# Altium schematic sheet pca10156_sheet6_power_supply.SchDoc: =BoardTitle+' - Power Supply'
size A3; Organization: Nordic Semiconductor; DocumentNumber: 6; SheetNumber: 6; SheetTotal: 7; CompanyName: Nordic Semiconductor; DocumentSize: A4
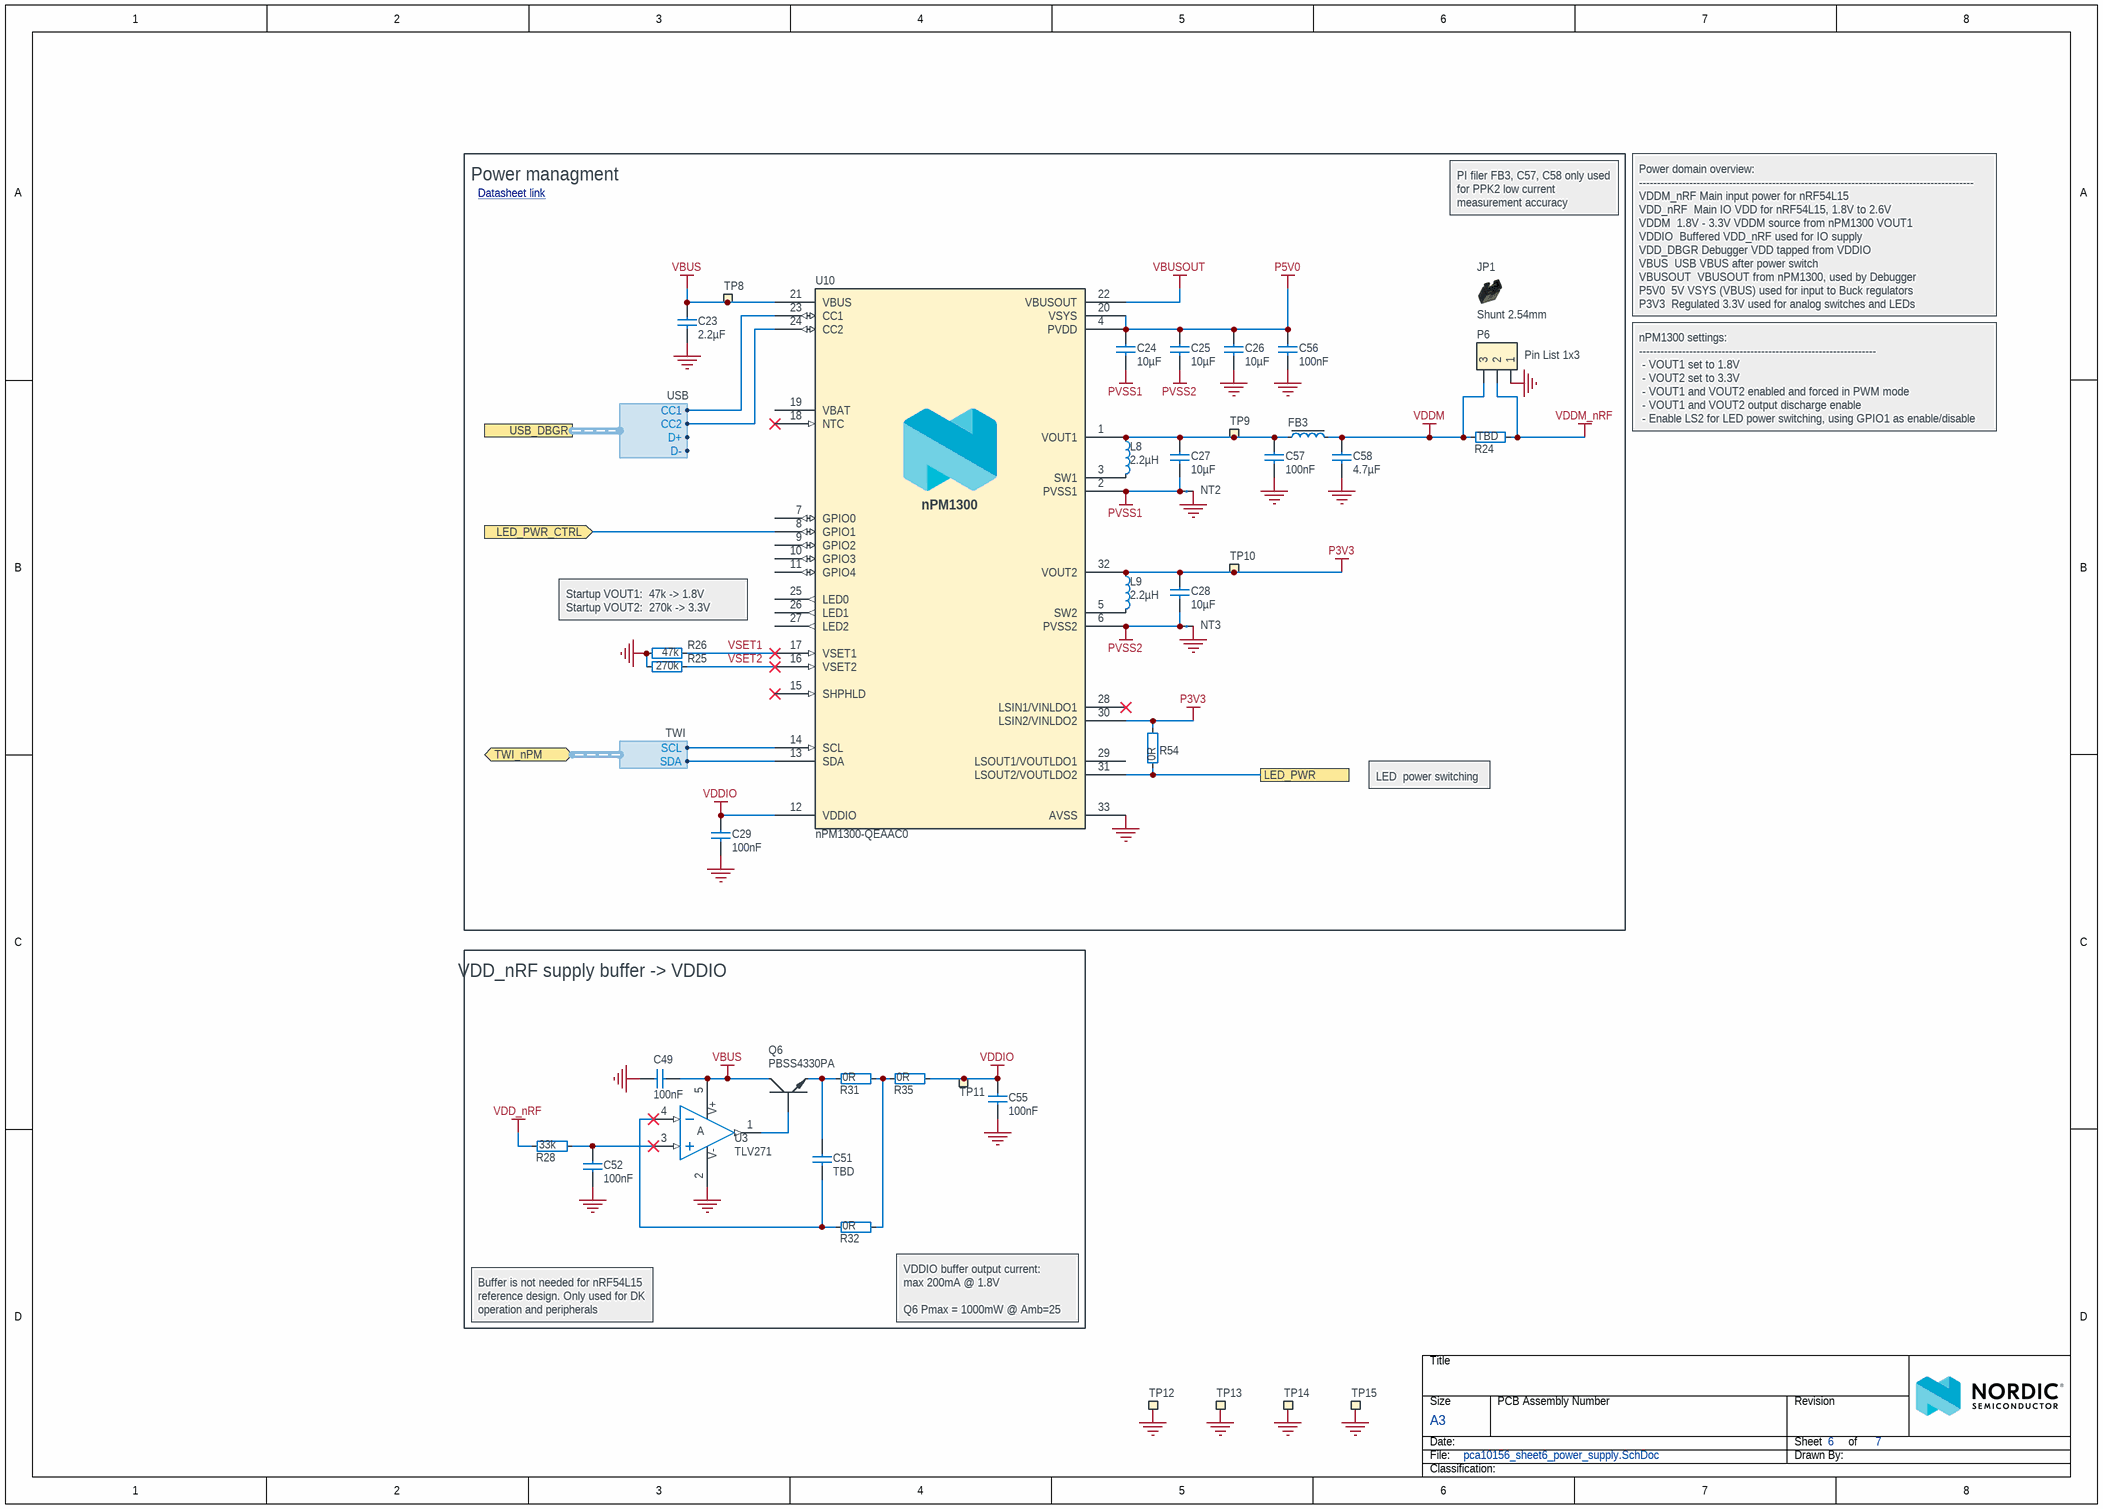
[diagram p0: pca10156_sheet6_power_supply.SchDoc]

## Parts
C23  2.2µF  [CAPC1005X04L]
C24  10µF  [CAPC1608X06L]
C25  10µF  [CAPC1608X06L]
C26  10µF  [CAPC1608X06L]
C27  10µF  [CAPC1608X06L]
C28  10µF  [CAPC1608X06L]
C29  100nF  [CAPC0603X03L_C]
C49  100nF  [CAPC0603X03L_C]
C51  TBD  [CAPC0603X03L_C]
C52  100nF  [CAPC0603X03L_C]
C55  100nF  [CAPC0603X03L_C]
C56  100nF  [CAPC0603X03L_C]
C57  100nF  [CAPC0603X03L_C]
C58  4.7µF  [CAPC1608X06L]
FB3  120R/0.55A  [INDC1005X04L]  (value not drawn)
JP1  Shunt 2.54mm  [Shunt_2.54mm_Vertical]
L8  2.2µH  [INDC2016X10N]
L9  2.2µH  [INDC2016X10N]
NT2  Net tie  [2 PIN STARPOINT]  (value not drawn)  (net tie, no BOM)
NT3  Net tie  [2 PIN STARPOINT]  (value not drawn)  (net tie, no BOM)
P6  Pin List 1x3  [LIST_1x3_SMD]
Q6  PBSS4330PA  [DFN105P200X65-3N_v2]
R24  TBD  [RESC1005X04L]
R25  270k  [RESC0603X03L_C]
R26  47k  [RESC0603X03L_C]
R28  33k  [RESC0603X03L_C]
R31  0R  [RESC0603X03L_C]
R32  0R  [RESC0603X03L_C]
R35  0R  [RESC0603X03L_C]
R54  0R  [RESC0603X03L_C]
TP8  Ø1.5mm,SMD  [TP_SMD_D1.5mm]  (value not drawn)  (no BOM)
TP9  Ø1.5mm,SMD  [TP_SMD_D1.5mm]  (value not drawn)  (no BOM)
TP10  Ø1.5mm,SMD  [TP_SMD_D1.5mm]  (value not drawn)  (no BOM)
TP11  Ø1.5mm,SMD  [TP_SMD_D1.5mm]  (value not drawn)  (no BOM)
TP12  Ø1.5mm,SMD  [TP_SMD_D1.5mm]  (value not drawn)  (no BOM)
TP13  Ø1.5mm,SMD  [TP_SMD_D1.5mm]  (value not drawn)  (no BOM)
TP14  Ø1.5mm,SMD  [TP_SMD_D1.5mm]  (value not drawn)  (no BOM)
TP15  Ø1.5mm,SMD  [TP_SMD_D1.5mm]  (value not drawn)  (no BOM)
U3  TLV271  [SOT95P280X145-5N]
U10  nPM1300-QEAAC0  [Nordic_QFN50P500X500X90-33N]

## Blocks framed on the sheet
Power managment: C23-C29 C56-C58 FB3 JP1 L8 L9 NT2 NT3 P6 R24-R26 R54 TP8-TP10 U10
VDD_nRF supply buffer -> VDDIO: C49 C51 C52 C55 Q6 R28 R31 R32 R35 TP11 U3

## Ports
LED_PWR, LED_PWR_CTRL (in), TWI_nPM (bidir, harness TWI), USB_DBGR (harness USB)

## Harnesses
TWI: SDA, SCL
USB: D+, D-, CC1, CC2

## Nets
GND: C23.1 C26.1 C29.2 C49.2 C52.2 C55.2 C56.1 C57.1 C58.2 NT2.1 NT3.1 P6.1 R25.2 R26.2 TP12.1 TP13.1 TP14.1 TP15.1 U3.2(VSS) U10.33(AVSS)
P3V3: C28.2 L9.1 R54.2 TP10.1 U10.30(LSIN2/VINLDO2) U10.32(VOUT2)
P5V0: C24.2 C25.2 C26.2 C56.2 U10.4(PVDD) U10.20(VSYS)
PVSS1: C24.1 C27.1 NT2.2 U10.2(PVSS1)
PVSS2: C25.1 C28.1 NT3.2 U10.6(PVSS2)
VBUS: C23.2 C49.1 Q6.3(C) TP8.1 U3.5(VDD) U10.21(VBUS)
VBUSOUT: U10.22(VBUSOUT)
VDD_nRF: R28.1
VDDIO: C29.1 C55.1 R35.2 TP11.1 U10.12(VDDIO)
VDDM: C58.1 FB3.2 P6.3 R24.2
VDDM_nRF: P6.2 R24.1
LED_PWR: R54.1 U10.31(LSOUT2/VOUTLDO2) ; port LED_PWR
LED_PWR_CTRL: U10.8(GPIO1) ; port LED_PWR_CTRL
VSET1: R26.1 U10.17(VSET1)
VSET2: R25.1 U10.16(VSET2)
NetC27_2: C27.2 C57.2 FB3.1 L8.1 TP9.1 U10.1(VOUT1)
NetC51_1: C51.1 R32.1 U3.4(IN-)
NetC51_2: C51.2 Q6.2(E) R31.1
NetC52_1: C52.1 R28.2 U3.3(IN+)
NetL8_2: L8.2 U10.3(SW1)
NetL9_2: L9.2 U10.5(SW2)
NetQ6_1: Q6.1(B) U3.1(OUT)
NetR31_2: R31.2 R32.2 R35.1
NetU10_13: U10.13(SDA) ; port TWI_nPM.SDA
NetU10_14: U10.14(SCL) ; port TWI_nPM.SCL
NetU10_23: U10.23(CC1) ; port USB_DBGR.CC1
NetU10_24: U10.24(CC2) ; port USB_DBGR.CC2

Not connected (* = marked no-connect by the designer): U10 7(GPIO0) 9(GPIO2) 10(GPIO3) 11(GPIO4) 15(SHPHLD)* 18(NTC)* 19(VBAT) 25(LED0) 26(LED1) 27(LED2) 28(LSIN1/VINLDO1)* 29(LSOUT1/VOUTLDO1)

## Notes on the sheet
- Datasheet link <https://infocenter.nordicsemi.com/index.jsp?topic=%2Fstruct_pmic%2Fstruct%2Fnpm1300.html>
- PI filer FB3, C57, C58 only used for PPK2 low current measurement accuracy
- Power domain overview:
  ---------------------------------------------------------------------------------------------
  VDDM_nRF	Main input power for nRF54L15
  VDD_nRF		Main IO VDD for nRF54L15, 1.8V to 2.6V
  VDDM		1.8V - 3.3V VDDM source from nPM1300 VOUT1
  VDDIO		Buffered VDD_nRF used for IO supply
  VDD_DBGR	Debugger VDD tapped from VDDIO
  VBUS		USB VBUS after power switch
  VBUSOUT		VBUSOUT from nPM1300, used by Debugger
  P5V0		5V VSYS (VBUS) used for input to Buck regulators
  P3V3		Regulated 3.3V used for analog switches and LEDs
- nPM1300 settings:
  ------------------------------------------------------------------
  - VOUT1 set to 1.8V
  - VOUT2 set to 3.3V
  - VOUT1 and VOUT2 enabled and forced in PWM mode
  - VOUT1 and VOUT2 output discharge enable
  - Enable LS2 for LED power switching, using GPIO1 as enable/disable signal.
- Startup VOUT1:  47k -> 1.8V
  Startup VOUT2:  270k -> 3.3V
- LED  power switching
- Buffer is not needed for nRF54L15 reference design. Only used for DK operation and peripherals
- (near R32) VDDIO buffer output current:
  max 200mA @ 1.8V
  Q6 Pmax = 1000mW @ Amb=25

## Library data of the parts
C23 = C0402-2µ2-10V: Capacitor, X5R, ±10%; Manufacturer: N.A.; Part number NEMS: 100200376; Component Status: Active; Pad Count: 2; Note: 10V
C24-C28 = C0603-10µ-10V-X7T-GRM188D71A106MA73: Capacitor, X7T, ±20%, 10V; Manufacturer: Murata; Part number IPS: 00000004696; Part number NEMS: 100200414; Component Status: Active; Pad Count: 2; Note: 10VDC; Artikkelnr Noca: N.A.
C29 C49 C52 C55 = C0201-100n: Capacitor, X5R, ±10%; Manufacturer: N.A.; Part number IPS: 00000001248, 00000002505; Part number Norautron: 262071862; Part number NEMS: 100200078; Pad Count: 2; Note: 16V; Component Status: Active
C51 = C0201-TBD: Chip Cap 0201; Manufacturer: N.A.; Part number NEMS: 100200002; Component Status: Active; Pad Count: 2; Assembly: Not Mounted
C56 = C0201-100n: Capacitor, X5R, ±10%; Manufacturer: N.A.; Part number IPS: 00000001248, 00000002505; Part number Norautron: 262071862; Part number NEMS: 100200078; Note: 16V; Assembly: Not Mounted; Pad Count: 2; Component Status: Active
C57 = C0201-100n: Capacitor, X5R, ±10%; Manufacturer: N.A.; Part number IPS: 00000001248, 00000002505; Part number Norautron: 262071862; Part number NEMS: 100200078; Note: 16V; Pad Count: 2; Component Status: Active
C58 = C0603-4µ7-10V-X7S: Capacitor, X7S, ±10%, 10V; Manufacturer: N.A.; Part number IPS: 00000001779; Part number NEMS: 100200351; Pad Count: 2; Artikkelnr Noca: 20030013; Component Status: Active
FB3 = FB0402-120R@100M-500mA: Ferrite Bead, 120 Ohm @ 100MHz, 500mA, 250 mOhm Max; Manufacturer: Murata; Manufacturer Part Number: BLM15AG121SN1D; Part number IPS: 00000009954; Part number Norautron: 265230631; Part number NEMS: 100300099; Note: Chip EMIFIL Inductor Type Chip Ferrite Bead; Artikkelnr Noca: 33029317; Pad Count: 2; Component Status: Active
JP1 = SHUNT JUMPER 2.54mm Black Vertical: Shunt Jumper 2.54mm Black, open top; Manufacturer: WCON; Manufacturer Part Number: 3710-6001OS0B05; Part number NEMS: 100500728; Pad Count: 2; Note: N.A.; Component Status: Active; System: Connector
L8 L9 = L0806-2µ2-2500mA-73mOhm-CIGT201610EH2R2MNE: Inductor, Irms=2.5A, Isat=2.9A, ±20%, DCR=73mΩ; Manufacturer: Samsung Electro-Mechanics America; Part number Norautron: 26521789; Part number NEMS: 100300400; Component Status: Active; Pad Count: 2; Note: Unshielded Thin Film Inductor; Artikkelnr Noca: N.A.
NT2 NT3 = 2 pin starpoint: Starpoint; Manufacturer: N.A.; Part number NEMS: 100500603; Pad Count: 2; Component Status: Active; System: Connector
P6 = Pin List 1x3 SMD: Pin List 1x3, 2.54mm (100mil), SMD; Manufacturer: WCON; Manufacturer Part Number: 1125-1103S0M116CR04; Part number Norautron: 26470016; Part number NEMS: 100500306; Note: N.A.; Pad Count: 3; Component Status: Active; System: Connector
Q6 = PBSS4330PA,115: 30V, 3A, 2.1W, G=270, NPN Transistor; Manufacturer: Nexperia; Part number NEMS: 101300184; Component Status: Active; Pad Count: 3; Note: N.A.
R24 = R0402-TBD: Chip Res 0402; Manufacturer: N.A.; Part number NEMS: 100100282; Component Status: Active; Pad Count: 2; Assembly: Not Mounted
R25 = R0201-270k: Resistor, ±1%, 0.05W; Manufacturer: N.A.; Part number IPS: 00000004317; Part number NEMS: 100100086; Component Status: Active; Pad Count: 2; Note: Chip Res 1%
R26 = R0201-47k: Resistor, ±1%, 0.05W; Manufacturer: N.A.; Part number IPS: 00000001423; Part number NEMS: 100100076; Component Status: Active; Pad Count: 2; Note: Chip Res 1%
R28 = R0201-33k: Resistor, ±1%, 0.05W; Manufacturer: N.A.; Part number IPS: 00000001708; Part number NEMS: 100100073; Component Status: Active; Pad Count: 2; Note: Chip Res 1%
R31 R32 R35 = R0201-0R: Resistor, ±5%, 0.05W; Manufacturer: N.A.; Part number IPS: 00000003245; Part number NEMS: 100100001; Component Status: Active; Pad Count: 2; Note: Chip Res 5%
R54 = R0201-0R: Resistor, ±5%, 0.05W; Manufacturer: N.A.; Part number IPS: 00000003245; Part number NEMS: 100100001; Component Status: Active; Pad Count: 2; Note: Chip Res 5%; Assembly: Not Mounted
TP8-TP15 = TP_SMD_Ø1.5MM: 1.5mm circular SMD testpad; Manufacturer: Nordic Semiconductor; Manufacturer Part Number: N.A.; Part number NEMS: 100500477; Pad Count: 1; Component Status: Active
U3 = TLV271CW5-7: Dual rail to rail CMOS Amplifier; Manufacturer: Diodes Incorporated; Part number NEMS: 101900398; Component Status: Active; Pad Count: 5; Note: N.A.
U10 = nPM1300-QEAAC0: Li-Ion/Li-Polymer USB-C battery charger with high efficiency buck regulators, LDOs or load switches, LED drivers, TWI and VBUSOUT; Manufacturer: Nordic Semiconductor; Part number NEMS: 102000306; Component Status: Active; Pad Count: 33; Note: Production version; Artikkelnr Noca: N.A.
